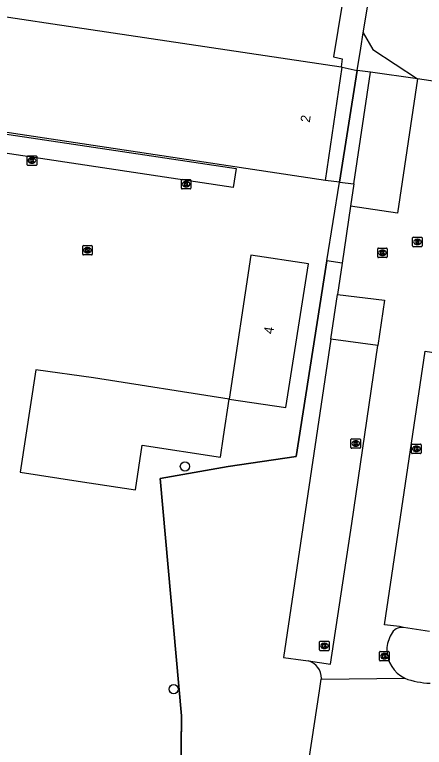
# Model space of a CAD drawing. Extents: x 161094 to 161705, y 379509 to 380907.
# Drawn here: x 161265 to 161308, y 380176.5 to 380253.5 of the extents above; entities that cross this region are included whole.
import ezdxf

# ---------------------------------------------------------------- set-up
doc = ezdxf.new("R2010")
doc.units = 0
for name, color, linetype in [('IMGEO_Boom', 7, 'Continuous'), ('IMGEO_Groenvoorziening', 7, 'Continuous'), ('IMGEO_Hek', 7, 'Continuous'), ('IMGEO_Kolk', 7, 'Continuous'), ('IMGEO_Loofbos', 7, 'Continuous'), ('IMGEO_Pand', 7, 'Continuous'), ('IMGEO_Pand_nummerreeks', 7, 'Continuous'), ('IMGEO_Parkeervlak_gesloten', 7, 'Continuous'), ('IMGEO_Rijbaan_lokaal_gesloten', 7, 'Continuous'), ('IMGEO_Rioolput', 7, 'Continuous'), ('IMGEO_Voetpad_gesloten', 7, 'Continuous'), ('IMGEO_Voetpad_open', 7, 'Continuous')]:
    doc.layers.add(name, color=color, linetype=linetype)

msp = doc.modelspace()

# ---------------------------------------------------------------- linework, layer by layer
at = {"layer": 'IMGEO_Boom'}
for centre in [(161282.853, 380206.062), (161281.668, 380182.662)]:
    msp.add_circle(centre, 0.489, dxfattribs=at)
at = {"layer": 'IMGEO_Groenvoorziening'}
for points in [[(161299.857, 380257.63), (161298.444, 380249.078), (161299.367, 380248.873), (161299.247, 380248.027)], [(161301.587, 380251.619), (161301.812, 380253.032), (161302.475, 380257.198)], [(161300.955, 380247.653), (161301.329, 380250), (161301.587, 380251.619)], [(161301.587, 380251.619), (161302.585, 380249.848), (161307.284, 380246.773)]]:
    msp.add_lwpolyline(points, dxfattribs=at)
at = {"layer": 'IMGEO_Hek'}
for points in [[(161300.955, 380247.653), (161301.329, 380250), (161301.587, 380251.619), (161301.812, 380253.032), (161302.475, 380257.198)], [(161299.089, 380235.933), (161300.955, 380247.653)], [(161297.773, 380227.67), (161299.089, 380235.933)], [(161287.389, 380206.038), (161294.54, 380207.121), (161297.773, 380227.67)], [(161280.254, 380204.807), (161287.389, 380206.038)], [(161282.224, 380153.845), (161282.498, 380179.855), (161280.254, 380204.807)]]:
    msp.add_lwpolyline(points, dxfattribs=at)
at = {"layer": 'IMGEO_Kolk'}
for p, q in [((161266.273, 380237.763), (161266.273, 380238.615)), ((161266.348, 380238.689), (161267.2, 380238.689)), ((161266.761, 380238.469), (161266.786, 380238.469)), ((161267.274, 380238.615), (161267.274, 380237.763)), ((161267.2, 380237.689), (161266.348, 380237.689)), ((161266.784, 380237.909), (161266.759, 380237.909)), ((161282.471, 380235.283), (161282.471, 380236.135)), ((161282.546, 380236.209), (161283.398, 380236.209)), ((161283.472, 380236.135), (161283.472, 380235.283)), ((161282.982, 380235.429), (161282.957, 380235.429)), ((161282.959, 380235.989), (161282.984, 380235.989)), ((161283.398, 380235.209), (161282.546, 380235.209)), ((161272.109, 380228.348), (161272.109, 380229.2)), ((161272.184, 380229.274), (161273.036, 380229.274)), ((161273.11, 380229.2), (161273.11, 380228.348)), ((161272.62, 380228.494), (161272.595, 380228.494)), ((161272.597, 380229.054), (161272.622, 380229.054)), ((161303.099, 380228.074), (161303.099, 380228.926)), ((161303.174, 380229), (161304.026, 380229)), ((161303.587, 380228.78), (161303.612, 380228.78)), ((161304.1, 380228.926), (161304.1, 380228.074)), ((161273.036, 380228.274), (161272.184, 380228.274)), ((161304.026, 380228), (161303.174, 380228)), ((161303.61, 380228.22), (161303.585, 380228.22)), ((161300.294, 380208.038), (161300.294, 380208.89)), ((161300.369, 380208.964), (161301.221, 380208.964)), ((161300.782, 380208.744), (161300.807, 380208.744)), ((161301.295, 380208.89), (161301.295, 380208.038)), ((161306.737, 380208.408), (161307.589, 380208.408)), ((161301.221, 380207.964), (161300.369, 380207.964)), ((161300.805, 380208.184), (161300.78, 380208.184)), ((161306.662, 380207.482), (161306.662, 380208.334)), ((161307.173, 380207.628), (161307.148, 380207.628)), ((161307.15, 380208.188), (161307.175, 380208.188)), ((161307.663, 380208.334), (161307.663, 380207.482)), ((161307.589, 380207.408), (161306.737, 380207.408)), ((161296.997, 380186.779), (161296.997, 380187.631)), ((161297.072, 380187.705), (161297.924, 380187.705)), ((161297.998, 380187.631), (161297.998, 380186.779)), ((161297.508, 380186.925), (161297.483, 380186.925)), ((161297.485, 380187.485), (161297.51, 380187.485)), ((161297.924, 380186.705), (161297.072, 380186.705)), ((161303.301, 380185.704), (161303.301, 380186.556)), ((161303.376, 380186.63), (161304.228, 380186.63)), ((161303.789, 380186.41), (161303.814, 380186.41)), ((161304.302, 380186.556), (161304.302, 380185.704)), ((161304.228, 380185.63), (161303.376, 380185.63)), ((161303.812, 380185.85), (161303.787, 380185.85))]:
    msp.add_line(p, q, dxfattribs=at)
for points in [[(161266.273, 380237.763), (161266.273, 380238.615)], [(161266.348, 380238.689), (161267.2, 380238.689)], [(161267.274, 380238.615), (161267.274, 380237.763)], [(161267.2, 380237.689), (161266.348, 380237.689)], [(161266.594, 380238.389), (161266.717, 380238.389), (161266.717, 380238.238), (161266.847, 380238.389), (161267.011, 380238.389), (161266.865, 380238.238), (161267.018, 380237.989), (161266.866, 380237.989), (161266.781, 380238.153), (161266.717, 380238.086), (161266.717, 380237.989), (161266.594, 380237.989), (161266.594, 380238.389)], [(161282.471, 380235.283), (161282.471, 380236.135)], [(161282.546, 380236.209), (161283.398, 380236.209)], [(161283.472, 380236.135), (161283.472, 380235.283)], [(161282.792, 380235.909), (161282.915, 380235.909), (161282.915, 380235.758), (161283.045, 380235.909), (161283.209, 380235.909), (161283.063, 380235.758), (161283.216, 380235.509), (161283.064, 380235.509), (161282.979, 380235.673), (161282.915, 380235.606), (161282.915, 380235.509), (161282.792, 380235.509), (161282.792, 380235.909)], [(161283.398, 380235.209), (161282.546, 380235.209)], [(161272.109, 380228.348), (161272.109, 380229.2)], [(161272.184, 380229.274), (161273.036, 380229.274)], [(161273.11, 380229.2), (161273.11, 380228.348)], [(161272.43, 380228.974), (161272.553, 380228.974), (161272.553, 380228.823), (161272.683, 380228.974), (161272.847, 380228.974), (161272.701, 380228.823), (161272.854, 380228.574), (161272.702, 380228.574), (161272.617, 380228.738), (161272.553, 380228.671), (161272.553, 380228.574), (161272.43, 380228.574), (161272.43, 380228.974)], [(161303.099, 380228.074), (161303.099, 380228.926)], [(161303.174, 380229), (161304.026, 380229)], [(161303.42, 380228.7), (161303.543, 380228.7), (161303.543, 380228.549), (161303.673, 380228.7), (161303.837, 380228.7), (161303.691, 380228.549), (161303.844, 380228.3), (161303.692, 380228.3), (161303.607, 380228.464), (161303.543, 380228.397), (161303.543, 380228.3), (161303.42, 380228.3), (161303.42, 380228.7)], [(161304.1, 380228.926), (161304.1, 380228.074)], [(161273.036, 380228.274), (161272.184, 380228.274)], [(161304.026, 380228), (161303.174, 380228)], [(161300.294, 380208.038), (161300.294, 380208.89)], [(161300.369, 380208.964), (161301.221, 380208.964)], [(161300.615, 380208.664), (161300.738, 380208.664), (161300.738, 380208.513), (161300.868, 380208.664), (161301.032, 380208.664), (161300.886, 380208.513), (161301.039, 380208.264), (161300.887, 380208.264), (161300.802, 380208.428), (161300.738, 380208.361), (161300.738, 380208.264), (161300.615, 380208.264), (161300.615, 380208.664)], [(161301.295, 380208.89), (161301.295, 380208.038)], [(161306.737, 380208.408), (161307.589, 380208.408)], [(161301.221, 380207.964), (161300.369, 380207.964)], [(161306.662, 380207.482), (161306.662, 380208.334)], [(161306.983, 380208.108), (161307.106, 380208.108), (161307.106, 380207.957), (161307.236, 380208.108), (161307.4, 380208.108), (161307.254, 380207.957), (161307.407, 380207.708), (161307.255, 380207.708), (161307.17, 380207.872), (161307.106, 380207.805), (161307.106, 380207.708), (161306.983, 380207.708), (161306.983, 380208.108)], [(161307.663, 380208.334), (161307.663, 380207.482)], [(161307.589, 380207.408), (161306.737, 380207.408)], [(161296.997, 380186.779), (161296.997, 380187.631)], [(161297.072, 380187.705), (161297.924, 380187.705)], [(161297.998, 380187.631), (161297.998, 380186.779)], [(161297.318, 380187.405), (161297.441, 380187.405), (161297.441, 380187.254), (161297.571, 380187.405), (161297.735, 380187.405), (161297.589, 380187.254), (161297.742, 380187.005), (161297.59, 380187.005), (161297.505, 380187.169), (161297.441, 380187.102), (161297.441, 380187.005), (161297.318, 380187.005), (161297.318, 380187.405)], [(161297.924, 380186.705), (161297.072, 380186.705)], [(161303.301, 380185.704), (161303.301, 380186.556)], [(161303.376, 380186.63), (161304.228, 380186.63)], [(161303.622, 380186.33), (161303.745, 380186.33), (161303.745, 380186.179), (161303.875, 380186.33), (161304.039, 380186.33), (161303.893, 380186.179), (161304.046, 380185.93), (161303.894, 380185.93), (161303.809, 380186.094), (161303.745, 380186.027), (161303.745, 380185.93), (161303.622, 380185.93), (161303.622, 380186.33)], [(161304.302, 380186.556), (161304.302, 380185.704)], [(161304.228, 380185.63), (161303.376, 380185.63)]]:
    msp.add_lwpolyline(points, dxfattribs=at)
for centre, start, end in [((161266.35, 380238.613), 91.55205, 178.44795), ((161266.35, 380238.613), 91.55205, 178.44795), ((161267.198, 380238.613), 1.55205, 88.44795), ((161267.198, 380238.613), 1.55205, 88.44795), ((161266.35, 380237.765), 181.55205, 268.44795), ((161266.35, 380237.765), 181.55205, 268.44795), ((161267.198, 380237.765), 271.55205, 358.44795), ((161267.198, 380237.765), 271.55205, 358.44795), ((161282.548, 380236.133), 91.55205, 178.44795), ((161282.548, 380236.133), 91.55205, 178.44795), ((161283.396, 380236.133), 1.55205, 88.44795), ((161283.396, 380236.133), 1.55205, 88.44795), ((161282.548, 380235.285), 181.55205, 268.44795), ((161282.548, 380235.285), 181.55205, 268.44795), ((161283.396, 380235.285), 271.55205, 358.44795), ((161283.396, 380235.285), 271.55205, 358.44795), ((161272.186, 380229.198), 91.55205, 178.44795), ((161272.186, 380229.198), 91.55205, 178.44795), ((161273.034, 380229.198), 1.55205, 88.44795), ((161273.034, 380229.198), 1.55205, 88.44795), ((161303.176, 380228.924), 91.55205, 178.44795), ((161303.176, 380228.924), 91.55205, 178.44795), ((161304.024, 380228.924), 1.55205, 88.44795), ((161304.024, 380228.924), 1.55205, 88.44795), ((161272.186, 380228.35), 181.55205, 268.44795), ((161272.186, 380228.35), 181.55205, 268.44795), ((161273.034, 380228.35), 271.55205, 358.44795), ((161273.034, 380228.35), 271.55205, 358.44795), ((161303.176, 380228.076), 181.55205, 268.44795), ((161303.176, 380228.076), 181.55205, 268.44795), ((161304.024, 380228.076), 271.55205, 358.44795), ((161304.024, 380228.076), 271.55205, 358.44795), ((161300.371, 380208.888), 91.55205, 178.44795), ((161300.371, 380208.888), 91.55205, 178.44795), ((161301.219, 380208.888), 1.55205, 88.44795), ((161301.219, 380208.888), 1.55205, 88.44795), ((161306.739, 380208.332), 91.55205, 178.44795), ((161306.739, 380208.332), 91.55205, 178.44795), ((161307.587, 380208.332), 1.55205, 88.44795), ((161307.587, 380208.332), 1.55205, 88.44795), ((161300.371, 380208.04), 181.55205, 268.44795), ((161300.371, 380208.04), 181.55205, 268.44795), ((161301.219, 380208.04), 271.55205, 358.44795), ((161301.219, 380208.04), 271.55205, 358.44795), ((161306.739, 380207.484), 181.55205, 268.44795), ((161306.739, 380207.484), 181.55205, 268.44795), ((161307.587, 380207.484), 271.55205, 358.44795), ((161307.587, 380207.484), 271.55205, 358.44795), ((161297.074, 380187.629), 91.55205, 178.44795), ((161297.074, 380187.629), 91.55205, 178.44795), ((161297.922, 380187.629), 1.55205, 88.44795), ((161297.922, 380187.629), 1.55205, 88.44795), ((161297.074, 380186.781), 181.55205, 268.44795), ((161297.074, 380186.781), 181.55205, 268.44795), ((161297.922, 380186.781), 271.55205, 358.44795), ((161297.922, 380186.781), 271.55205, 358.44795), ((161303.378, 380186.554), 91.55205, 178.44795), ((161303.378, 380186.554), 91.55205, 178.44795), ((161304.226, 380186.554), 1.55205, 88.44795), ((161304.226, 380186.554), 1.55205, 88.44795), ((161303.378, 380185.706), 181.55205, 268.44795), ((161303.378, 380185.706), 181.55205, 268.44795), ((161304.226, 380185.706), 271.55205, 358.44795), ((161304.226, 380185.706), 271.55205, 358.44795)]:
    msp.add_arc(centre, 0.0765, start, end, dxfattribs=at)
for centre, major_axis, ratio, start_param, end_param in [((161266.76, 380238.189), (-0.387, 0.002), 0.722429, 4.712389, 7.853982), ((161266.785, 380238.189), (-0.39, 0.002), 0.717154, 1.570796, 4.712389), ((161282.958, 380235.709), (-0.387, 0.002), 0.722429, 4.712389, 7.853982), ((161282.983, 380235.709), (-0.39, 0.002), 0.717154, 1.570796, 4.712389), ((161272.596, 380228.774), (-0.387, 0.002), 0.722429, 4.712389, 7.853982), ((161272.621, 380228.774), (-0.39, 0.002), 0.717154, 1.570796, 4.712389), ((161303.586, 380228.5), (-0.387, 0.002), 0.722429, 4.712389, 7.853982), ((161303.611, 380228.5), (-0.39, 0.002), 0.717154, 1.570796, 4.712389), ((161300.781, 380208.464), (-0.387, 0.002), 0.722429, 4.712389, 7.853982), ((161300.806, 380208.464), (-0.39, 0.002), 0.717154, 1.570796, 4.712389), ((161307.149, 380207.908), (-0.387, 0.002), 0.722429, 4.712389, 7.853982), ((161307.174, 380207.908), (-0.39, 0.002), 0.717154, 1.570796, 4.712389), ((161297.484, 380187.205), (-0.387, 0.002), 0.722429, 4.712389, 7.853982), ((161297.509, 380187.205), (-0.39, 0.002), 0.717154, 1.570796, 4.712389), ((161303.788, 380186.13), (-0.387, 0.002), 0.722429, 4.712389, 7.853982), ((161303.813, 380186.13), (-0.39, 0.002), 0.717154, 1.570796, 4.712389)]:
    msp.add_ellipse(centre, major_axis=major_axis, ratio=ratio, start_param=start_param, end_param=end_param, dxfattribs=at)
at = {"layer": 'IMGEO_Loofbos'}
msp.add_lwpolyline([(161297.773, 380227.67), (161294.54, 380207.121), (161287.389, 380206.038), (161280.254, 380204.807), (161282.498, 380179.855), (161282.167, 380149.06), (161269.88, 380149.639)], dxfattribs=at)
at = {"layer": 'IMGEO_Pand'}
for points in [[(161250.877, 380243.129), (161252.658, 380254.997), (161268.965, 380252.557), (161299.247, 380248.027)], [(161297.624, 380236.117), (161299.368, 380248.009)], [(161299.247, 380248.027), (161299.368, 380248.009)], [(161297.624, 380236.117), (161250.877, 380243.129)], [(161287.501, 380213.116), (161293.445, 380212.244), (161295.833, 380227.337), (161289.771, 380228.247), (161287.501, 380213.116)], [(161287.501, 380213.116), (161273.225, 380215.353), (161267.188, 380216.225), (161265.54, 380205.451), (161271.615, 380204.522), (161277.649, 380203.599), (161278.356, 380208.299), (161286.573, 380207.047), (161286.903, 380209.207), (161287.501, 380213.116)]]:
    msp.add_lwpolyline(points, dxfattribs=at)
at = {"layer": 'IMGEO_Parkeervlak_gesloten'}
for points in [[(161307.284, 380246.773), (161302.341, 380247.496)], [(161298.175, 380219.442), (161298.872, 380224.139)], [(161298.175, 380219.442), (161293.208, 380186.002), (161295.286, 380185.705), (161295.84, 380185.626)], [(161303.119, 380218.778), (161298.175, 380219.442)]]:
    msp.add_lwpolyline(points, dxfattribs=at)
at = {"layer": 'IMGEO_Rijbaan_lokaal_gesloten'}
for points in [[(161307.284, 380246.773), (161305.172, 380232.652), (161300.246, 380233.389)], [(161312.199, 380246.054), (161307.284, 380246.773)], [(161300.246, 380233.389), (161299.359, 380227.417)], [(161299.359, 380227.417), (161298.872, 380224.139)], [(161298.872, 380224.139), (161303.81, 380223.53), (161303.119, 380218.778)], [(161295.84, 380185.626), (161298.149, 380185.296), (161300.398, 380200.062), (161303.119, 380218.778)], [(161305.814, 380189.145), (161305.391, 380189.238), (161303.815, 380189.43), (161308.086, 380218.164), (161312.623, 380217.464), (161312.872, 380217.262)], [(161297.167, 380183.699), (161305.937, 380183.804)], [(161297.183, 380183.797), (161297.167, 380183.699)], [(161291.111, 380143.774), (161291.529, 380146.508), (161293.197, 380157.657), (161296.972, 380182.47), (161297.167, 380183.699)]]:
    msp.add_lwpolyline(points, dxfattribs=at)
for centre, radius, start, end in [((161305.665, 380187.903), 1.251, 83.14871, 156.08303), ((161307.609, 380186.653), 3.553, 150.3535, 176.92681), ((161307.482, 380186.857), 3.421, 180.22635, 243.14841), ((161295.299, 380183.821), 1.884, 359.25594, 73.32232), ((161308.837, 380191.679), 8.392, 249.78171, 268.44882)]:
    msp.add_arc(centre, radius, start, end, dxfattribs=at)
at = {"layer": 'IMGEO_Rioolput'}
for p, q in [((161306.771, 380229.222), (161306.771, 380230.074)), ((161306.846, 380230.148), (161307.698, 380230.148)), ((161307.259, 380229.928), (161307.284, 380229.928)), ((161307.772, 380230.074), (161307.772, 380229.222)), ((161307.282, 380229.368), (161307.257, 380229.368)), ((161307.698, 380229.148), (161306.846, 380229.148))]:
    msp.add_line(p, q, dxfattribs=at)
for points in [[(161306.771, 380229.222), (161306.771, 380230.074)], [(161306.846, 380230.148), (161307.698, 380230.148)], [(161307.772, 380230.074), (161307.772, 380229.222)], [(161307.36, 380229.846), (161307.108, 380229.848), (161307.108, 380229.448)], [(161307.108, 380229.448), (161307.232, 380229.448), (161307.232, 380229.61), (161307.243, 380229.61)], [(161307.286, 380229.767), (161307.232, 380229.767), (161307.232, 380229.686)], [(161307.232, 380229.686), (161307.284, 380229.686)], [(161307.29, 380229.581), (161307.361, 380229.448), (161307.501, 380229.448), (161307.436, 380229.574)], [(161307.698, 380229.148), (161306.846, 380229.148)]]:
    msp.add_lwpolyline(points, dxfattribs=at)
for centre, radius, start, end in [((161306.848, 380230.072), 0.0765, 91.55205, 178.44795), ((161306.848, 380230.072), 0.0765, 91.55205, 178.44795), ((161307.696, 380230.072), 0.0765, 1.55205, 88.44795), ((161307.696, 380230.072), 0.0765, 1.55205, 88.44795), ((161306.848, 380229.224), 0.0765, 181.55205, 268.44795), ((161306.848, 380229.224), 0.0765, 181.55205, 268.44795), ((161307.242, 380229.557), 0.0533, 26.02933, 88.69889), ((161307.268, 380229.875), 0.19, 274.7715, 282.96867), ((161307.292, 380229.671), 0.0964, 77.00612, 93.18647), ((161307.306, 380229.728), 0.0378, 276.66336, 79.67722), ((161307.359, 380229.736), 0.109, 350.36119, 89.41601), ((161307.357, 380229.736), 0.112, 277.58423, 350.98172), ((161307.341, 380229.521), 0.108, 29.51342, 73.79051), ((161307.696, 380229.224), 0.0765, 271.55205, 358.44795), ((161307.696, 380229.224), 0.0765, 271.55205, 358.44795)]:
    msp.add_arc(centre, radius, start, end, dxfattribs=at)
for centre, major_axis, ratio, start_param, end_param in [((161307.258, 380229.648), (-0.387, 0.002), 0.722429, 4.712389, 7.853982), ((161307.283, 380229.648), (-0.39, 0.002), 0.717154, 1.570796, 4.712389)]:
    msp.add_ellipse(centre, major_axis=major_axis, ratio=ratio, start_param=start_param, end_param=end_param, dxfattribs=at)
at = {"layer": 'IMGEO_Voetpad_gesloten'}
msp.add_lwpolyline([(161251.355, 380240.862), (161251.662, 380242.81), (161288.227, 380237.348), (161287.93, 380235.359), (161251.355, 380240.862)], dxfattribs=at)
at = {"layer": 'IMGEO_Voetpad_open'}
for points in [[(161300.955, 380247.653), (161299.089, 380235.933)], [(161299.368, 380248.009), (161300.955, 380247.653)], [(161302.341, 380247.496), (161300.955, 380247.653)], [(161300.596, 380235.744), (161302.341, 380247.496)], [(161299.089, 380235.933), (161297.624, 380236.117)], [(161297.773, 380227.67), (161299.089, 380235.933)], [(161299.089, 380235.933), (161300.596, 380235.744)], [(161300.596, 380235.744), (161300.246, 380233.389)], [(161299.359, 380227.417), (161297.773, 380227.67)], [(161308.533, 380188.732), (161305.814, 380189.145)]]:
    msp.add_lwpolyline(points, dxfattribs=at)

# ---------------------------------------------------------------- texts
at = {"layer": 'IMGEO_Pand_nummerreeks'}
for s, rotation, p in [('2', 81.65686, (161295.962, 380242.154)), ('4', 81.00924, (161292.107, 380219.916))]:
    msp.add_text(s, height=1, rotation=rotation, dxfattribs=at).set_placement(p)

doc.saveas('drawing.dxf')
